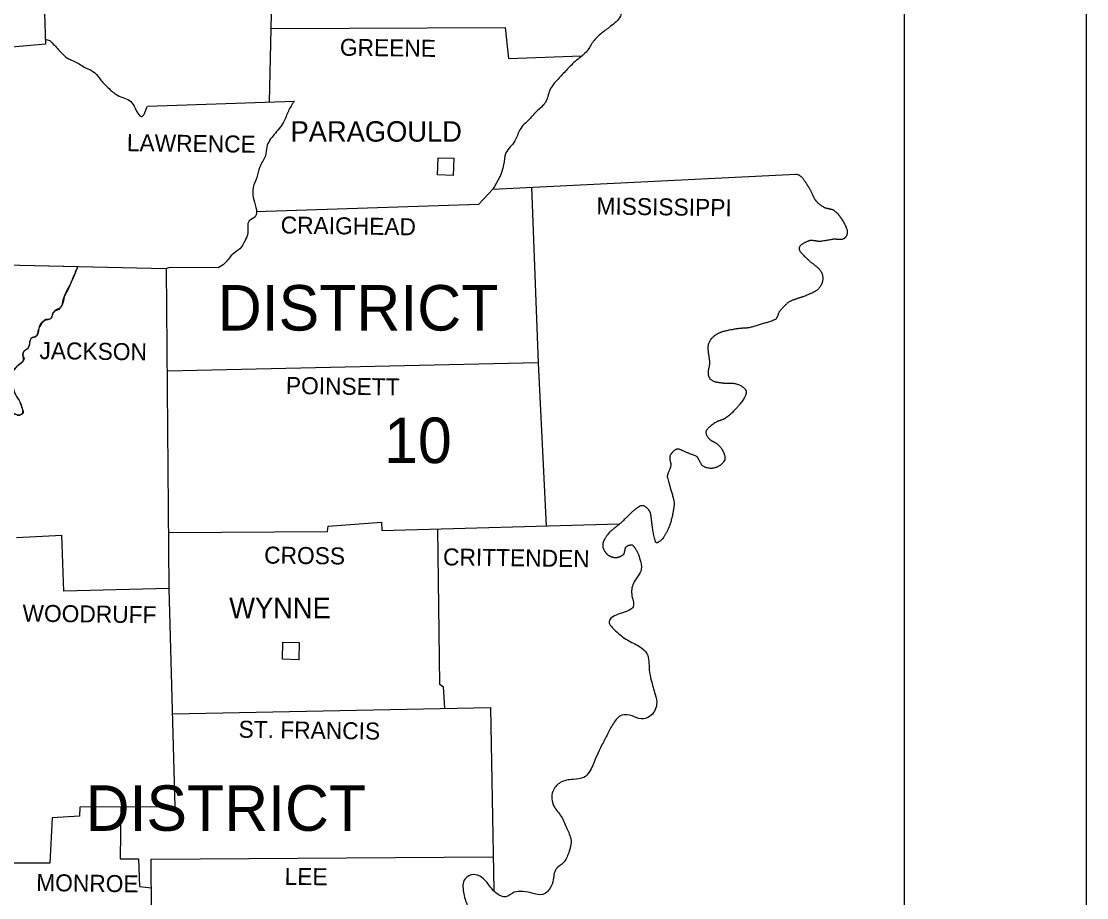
# Model space of a CAD drawing. Extents: x 840176 to 859715, y 1589036 to 1600368.
# Drawn here: x 855714 to 857176, y 1597585 to 1598788 of the extents above; entities that cross this region are included whole.
import ezdxf

# ---------------------------------------------------------------- set-up
doc = ezdxf.new("R2010")
doc.units = 0
for name, color, linetype in [('DSN_DRFT_Border', 7, 'Continuous'), ('SHET_Border-Text', 7, 'Continuous'), ('SHET_Stamp-Prelim', 7, 'Continuous')]:
    doc.layers.add(name, color=color, linetype=linetype)

msp = doc.modelspace()

# ---------------------------------------------------------------- linework, layer by layer
at = {"layer": 'DSN_DRFT_Border'}
for p, q in [((855753, 1598761.2), (855746.5, 1598763.1)), ((856088.1, 1598678.1), (856088.3, 1598678.4)), ((855706.8, 1598079.2), (855769.3, 1598082.6))]:
    msp.add_line(p, q, dxfattribs=at)
for points in [[(840175.5, 1600035.6), (840175.5, 1589035.6), (857175.5, 1589035.6), (857175.5, 1600035.6)], [(856284.8, 1598577), (856285.4, 1598600.6), (856306.9, 1598600), (856306.3, 1598576.4)], [(856071.9, 1597912.2), (856072.6, 1597935.9), (856095, 1597935.3), (856094.4, 1597911.6)]]:
    msp.add_lwpolyline(points, close=True, dxfattribs=at)
for points in [[(855654.4, 1598968.4), (855652.4, 1598951.7), (855663.3, 1598950.1), (855662.4, 1598943.9), (855675.1, 1598941.1), (855676.1, 1598932.1), (855682.3, 1598928.3), (855683.9, 1598902.2), (855715, 1598899.1), (855715.3, 1598875.1), (855726.8, 1598873.9), (855726.5, 1598864.5), (855736.5, 1598861.4), (855736.1, 1598829.7), (855744.5, 1598828.1), (855746.7, 1598756.6), (855700.4, 1598752.2), (855701, 1598737), (855687, 1598736), (855691.6, 1598453.7), (855912.3, 1598448.8), (855916, 1598009.3), (855771.9, 1598005.6), (855769.3, 1598082.6)], [(856054.1, 1598677.2), (856056.7, 1598797.9)], [(856056.3, 1598778), (856377.6, 1598779.6), (856381.9, 1598737), (856482.3, 1598740.4)], [(855886.5, 1598671.6), (856088.3, 1598678.4)], [(856360.7, 1598557.4), (856776.5, 1598578.2)], [(856035.9, 1598526.8), (856341.5, 1598536.8), (856360.7, 1598557.4)], [(856413.5, 1598560), (856422.7, 1598319.3), (856433.7, 1598095.2)], [(855983.9, 1598449.7), (855917.3, 1598450), (855912.3, 1598448.8)], [(856422.7, 1598319.3), (855913.5, 1598307.7)], [(855915.4, 1598086.2), (856133.9, 1598087.5), (856134.5, 1598094.9), (856207.9, 1598100.2), (856208.3, 1598089), (856534.6, 1598097.9)], [(856284.5, 1598091.1), (856287.6, 1597878), (856292.3, 1597874.6), (856294.3, 1597844.7)], [(855916, 1598009.3), (855924.4, 1597709.6), (855794, 1597709), (855793.4, 1597696.9), (855755.8, 1597694.4), (855752.6, 1597632.5), (855700.7, 1597632.1)], [(855920.9, 1597837.2), (856357.3, 1597846)], [(856357.3, 1597846), (856361.9, 1597595.2)], [(855850.1, 1597709.3), (855849.1, 1597638.1), (855874.3, 1597638.1), (855875.6, 1597600.4), (855892, 1597598.5)], [(855914.3, 1597152), (855965.5, 1597155.4), (855965.2, 1597266.2), (855924.7, 1597269.3), (855926.9, 1597486.5), (855892.7, 1597491.5), (855891.8, 1597637.8), (856361, 1597640.9)]]:
    msp.add_lwpolyline(points, dxfattribs=at)
for points in [[(856492.4, 1598984.7), (856495.2, 1598960.7), (856502.7, 1598948.3), (856503.9, 1598925.2), (856513.2, 1598915.3), (856529.1, 1598905.6), (856543.1, 1598889.4), (856546.2, 1598870.8), (856541.9, 1598851.8), (856540.9, 1598830.6), (856538.8, 1598812), (856535.6, 1598794.8), (856522.3, 1598781.1), (856509.8, 1598771.5), (856498.3, 1598760), (856490.2, 1598747.5), (856475.6, 1598734.5), (856461.6, 1598720.8), (856450.1, 1598708.6), (856438.9, 1598693.4), (856432.9, 1598676.6), (856420.8, 1598664.4), (856410.9, 1598653.5), (856397.5, 1598638.9), (856390.9, 1598623.7), (856378.5, 1598607.2), (856375.4, 1598590.7), (856360.7, 1598557.4)], [(855753, 1598761.2), (855764.8, 1598748.8), (855775.7, 1598738.2), (855787.5, 1598732.3), (855801.8, 1598724.2), (855814.3, 1598717.3), (855822.7, 1598707.1), (855833.9, 1598695.6), (855845.4, 1598686.5), (855863.7, 1598677.8), (855869.7, 1598668.5), (855878.1, 1598657), (855886.5, 1598671.6)], [(856088.1, 1598678.1), (856080, 1598664.7), (856073.5, 1598649.5), (856060.4, 1598632.4), (856050.5, 1598615.3), (856048.6, 1598603.4), (856040.8, 1598588.2), (856036.8, 1598573.3), (856031.8, 1598559.9), (856031.8, 1598546.2), (856035.5, 1598532.5), (856034.6, 1598519.7), (856026.2, 1598513.8), (856024.3, 1598497.9), (856020.6, 1598487), (856013.4, 1598475.8), (856003.2, 1598467.8), (855992.3, 1598455.3), (855983.9, 1598449.7)], [(855790.8, 1598451.5), (855780.6, 1598426.7), (855772.6, 1598410.2), (855767.9, 1598395.9), (855757.3, 1598387.8), (855753.9, 1598380), (855744.9, 1598376.9), (855737.7, 1598366), (855734.6, 1598356.3), (855726.8, 1598352), (855722.8, 1598339.5), (855715.9, 1598333), (855716.2, 1598322.1), (855708.1, 1598314.6), (855701.6, 1598305.9), (855701.3, 1598293.5), (855704.4, 1598277.9), (855710, 1598268.3), (855714.7, 1598256.4), (855714.4, 1598248.7), (855700.7, 1598248.7), (855688.8, 1598246.8)], [(856562.1, 1598051), (856564.3, 1598035.5), (856554.6, 1598018.4), (856551.2, 1598001.6), (856553.1, 1597984.4), (856535.6, 1597975.1), (856520.1, 1597963.9), (856529.1, 1597951.1), (856545.3, 1597938.7), (856561.8, 1597929.7), (856572.1, 1597920), (856575.2, 1597897.9), (856578, 1597883.3), (856583.3, 1597864), (856585.4, 1597850), (856575.8, 1597833.8), (856564.3, 1597830.4), (856551.8, 1597834.4), (856537.5, 1597835.4), (856526, 1597824.2), (856517.9, 1597809.2), (856509.8, 1597793.7), (856503.6, 1597780.6), (856497.7, 1597766.6), (856485.5, 1597750.1), (856470.9, 1597747.3), (856453.2, 1597742.9), (856442.9, 1597730.8), (856444.5, 1597710.6), (856454.4, 1597696.6), (856462.2, 1597679.8), (856467.8, 1597664.8), (856464.7, 1597646.5), (856457.2, 1597632.8), (856447.6, 1597624.4), (856442.9, 1597606.9), (856436.1, 1597593.9), (856429.2, 1597589.5), (856416.1, 1597590.8), (856402.1, 1597593.3), (856390, 1597592.3), (856378.2, 1597586.1), (856366.7, 1597590.1), (856354.8, 1597602.9), (856345.2, 1597612.9), (856334, 1597616.6), (856322.5, 1597610.7), (856320.3, 1597592.6), (856325.6, 1597574), (856330.9, 1597548.7), (856325.9, 1597533.8), (856324, 1597508.3)]]:
    msp.add_spline(points, degree=3, dxfattribs=at)
msp.add_open_spline([(856776.5, 1598578.2), (856778.6, 1598577.9), (856780.6, 1598577), (856782.4, 1598575.7), (856784.3, 1598574.3), (856785.9, 1598572.7), (856787.1, 1598570.8), (856788.5, 1598568.8), (856789.8, 1598566.8), (856791.1, 1598564.7), (856791.7, 1598563.7), (856792.3, 1598562.6), (856793, 1598561.6), (856793.6, 1598560.6), (856794.3, 1598559.6), (856794.9, 1598558.6), (856795.7, 1598557.3), (856796.5, 1598555.9), (856797.2, 1598554.5), (856797.9, 1598553.1), (856798.4, 1598551.7), (856799.1, 1598550.3), (856799.7, 1598548.9), (856800.4, 1598547.5), (856801.1, 1598546.1), (856801.7, 1598544.7), (856802.6, 1598543.4), (856803.6, 1598542.1), (856806.8, 1598538.2), (856810.7, 1598535.2), (856815.1, 1598532.8), (856816.2, 1598532.2), (856817.3, 1598531.7), (856818.5, 1598531.4), (856819.8, 1598531.2), (856821, 1598530.9), (856822.2, 1598530.7), (856823.4, 1598530.4), (856824.6, 1598530.1), (856825.8, 1598529.8), (856827, 1598529.5), (856828.1, 1598528.9), (856829.1, 1598528.1), (856833.6, 1598524.6), (856836.7, 1598520.4), (856839.7, 1598515.7), (856842.6, 1598511.2), (856844.9, 1598506.8), (856846.5, 1598501.7), (856846.9, 1598500.7), (856847, 1598499.6), (856847, 1598498.6), (856847, 1598497.5), (856846.9, 1598496.4), (856846.6, 1598495.3), (856846.3, 1598494.2), (856845.9, 1598493.2), (856845.3, 1598492.2), (856845, 1598491.7), (856844.6, 1598491.3), (856844.2, 1598490.9), (856844, 1598490.7), (856843.8, 1598490.5), (856843.5, 1598490.4), (856843.3, 1598490.2), (856843.1, 1598490), (856842.8, 1598489.8), (856841.6, 1598489.1), (856840.3, 1598488.6), (856838.9, 1598488.4), (856837.6, 1598488.3), (856836.3, 1598488.2), (856835, 1598488.3), (856833.7, 1598488.4), (856832.4, 1598488.6), (856831.1, 1598488.7), (856830.5, 1598488.7), (856829.8, 1598488.8), (856829.2, 1598488.7), (856828.5, 1598488.7), (856827.9, 1598488.7), (856827.3, 1598488.6), (856824.4, 1598488.1), (856821.7, 1598487.7), (856818.9, 1598487.2), (856816.1, 1598486.7), (856813.2, 1598486.3), (856810.4, 1598485.8), (856809.1, 1598485.6), (856807.8, 1598485.7), (856806.4, 1598485.9), (856805.1, 1598486), (856803.7, 1598486.4), (856802.4, 1598486.6), (856801, 1598486.8), (856799.7, 1598486.9), (856798.3, 1598487), (856797.6, 1598487.1), (856797, 1598487), (856796.3, 1598486.9), (856795.6, 1598486.8), (856794.9, 1598486.7), (856794.3, 1598486.4), (856792.7, 1598485.9), (856791.2, 1598485.2), (856789.6, 1598484.5), (856788.1, 1598483.7), (856786.6, 1598482.8), (856785.1, 1598481.8), (856783.8, 1598481), (856782.8, 1598480), (856781.8, 1598478.8), (856781.4, 1598478.3), (856781.2, 1598477.7), (856781, 1598477.2), (856780.9, 1598476.9), (856780.8, 1598476.6), (856780.8, 1598476.3), (856780.8, 1598476.1), (856780.8, 1598475.8), (856780.9, 1598475.5), (856781.2, 1598474.2), (856781.7, 1598473), (856782.5, 1598471.9), (856783.5, 1598470.6), (856784.4, 1598469.3), (856785.6, 1598468.2), (856788, 1598465.7), (856790.5, 1598463.3), (856793, 1598460.9), (856794.3, 1598459.7), (856795.6, 1598458.5), (856797, 1598457.4), (856798.3, 1598456.3), (856799.7, 1598455.3), (856801, 1598454.3), (856802.4, 1598453.2), (856803.7, 1598452.1), (856805.1, 1598451), (856806.5, 1598449.9), (856807.7, 1598448.6), (856808.9, 1598447.2), (856809.8, 1598446.2), (856810.6, 1598445), (856811.2, 1598443.8), (856811.9, 1598442.5), (856812.4, 1598441.3), (856812.8, 1598439.9), (856813.1, 1598438.6), (856813.3, 1598437.3), (856813.5, 1598436), (856813.6, 1598434.8), (856813.5, 1598433.5), (856813.2, 1598432.3), (856812.7, 1598429.5), (856811.7, 1598426.9), (856810.3, 1598424.4), (856809.5, 1598423.1), (856808.7, 1598422), (856807.6, 1598420.9), (856806.6, 1598419.8), (856805.5, 1598418.8), (856804.2, 1598418), (856801.5, 1598416.3), (856798.7, 1598414.8), (856795.7, 1598413.6), (856792.9, 1598412.4), (856790, 1598411.2), (856787.1, 1598410.2), (856785.7, 1598409.6), (856784.2, 1598409.1), (856782.8, 1598408.6), (856781.3, 1598408.1), (856779.8, 1598407.7), (856778.4, 1598407.2), (856776.9, 1598406.7), (856775.4, 1598406.2), (856774, 1598405.7), (856772.5, 1598405.2), (856771.1, 1598404.6), (856769.7, 1598404), (856768.2, 1598403.2), (856766.7, 1598402.4), (856765.4, 1598401.3), (856764, 1598400.3), (856762.8, 1598399.2), (856761.6, 1598398), (856760.4, 1598396.8), (856759.3, 1598395.6), (856758.1, 1598394.3), (856757, 1598393.1), (856755.8, 1598391.9), (856754.7, 1598390.6), (856753.9, 1598389.6), (856753.3, 1598388.5), (856752.8, 1598387.4), (856752.3, 1598386.2), (856752, 1598385), (856751.5, 1598383.8), (856751, 1598382.6), (856750.5, 1598381.5), (856749.9, 1598380.4), (856749.3, 1598379.4), (856748.3, 1598378.6), (856747.3, 1598378.1), (856744.5, 1598376.9), (856741.8, 1598375.9), (856738.9, 1598375), (856736.1, 1598374.2), (856733.3, 1598373.4), (856730.5, 1598372.5), (856727.6, 1598371.6), (856724.7, 1598370.7), (856721.8, 1598369.9), (856718.9, 1598369), (856716, 1598368.2), (856713, 1598367.5), (856711.8, 1598367.2), (856710.5, 1598367), (856709.2, 1598366.9), (856707.9, 1598366.8), (856706.6, 1598366.7), (856705.3, 1598366.6), (856704, 1598366.5), (856702.7, 1598366.5), (856701.4, 1598366.4), (856700.1, 1598366.3), (856698.8, 1598366.1), (856697.5, 1598366), (856694.6, 1598365.6), (856691.7, 1598365.1), (856688.9, 1598364.6), (856686, 1598364.1), (856683.2, 1598363.5), (856680.4, 1598362.9), (856678.8, 1598362.5), (856677.3, 1598362.1), (856675.7, 1598361.7), (856674.2, 1598361.2), (856672.8, 1598360.7), (856671.3, 1598360), (856669.8, 1598359.3), (856668.4, 1598358.6), (856667.1, 1598357.7), (856666.3, 1598357.2), (856665.7, 1598356.7), (856665, 1598356.2), (856664.3, 1598355.7), (856663.6, 1598355.1), (856662.9, 1598354.5), (856660.8, 1598352.5), (856659.1, 1598350.3), (856657.7, 1598347.8), (856657, 1598346.6), (856656.6, 1598345.4), (856656.3, 1598344.1), (856656, 1598342.8), (856655.8, 1598341.5), (856655.8, 1598340.2), (856655.8, 1598338.5), (856655.8, 1598336.8), (856656, 1598335.1), (856656.2, 1598333.4), (856656.4, 1598331.7), (856656.7, 1598330), (856656.9, 1598328.4), (856657.2, 1598326.7), (856657.4, 1598325), (856657.7, 1598323.3), (856657.9, 1598321.6), (856658, 1598319.9), (856658.1, 1598318.2), (856657.8, 1598316.4), (856657.5, 1598314.6), (856657.2, 1598312.8), (856656.7, 1598311.1), (856656.4, 1598309.3), (856656.1, 1598307.6), (856655.9, 1598305.8), (856656, 1598304), (856656, 1598303.1), (856656.2, 1598302.3), (856656.5, 1598301.4), (856656.6, 1598300.9), (856656.8, 1598300.5), (856657, 1598300.1), (856657.2, 1598299.6), (856657.4, 1598299.2), (856657.6, 1598298.8), (856658.5, 1598297.3), (856659.7, 1598296.1), (856661.2, 1598295.1), (856662.6, 1598294.2), (856664.1, 1598293.5), (856665.7, 1598293.2), (856667.4, 1598292.9), (856669, 1598292.5), (856670.7, 1598292.3), (856672.4, 1598292.1), (856674, 1598291.8), (856675.7, 1598291.6), (856677, 1598291.4), (856678.3, 1598291.3), (856679.6, 1598291.3), (856681, 1598291.3), (856682.3, 1598291.3), (856683.6, 1598291.4), (856685, 1598291.4), (856686.3, 1598291.4), (856687.6, 1598291.4), (856688.9, 1598291.4), (856690.2, 1598291.2), (856691.6, 1598291), (856694.5, 1598290.4), (856697.3, 1598289.5), (856700.1, 1598288.2), (856701.4, 1598287.5), (856702.7, 1598286.7), (856703.9, 1598285.8), (856704.5, 1598285.3), (856705, 1598284.8), (856705.6, 1598284.3), (856706.1, 1598283.8), (856706.6, 1598283.2), (856707.1, 1598282.6), (856707.8, 1598281.7), (856708.1, 1598280.7), (856708.3, 1598279.7), (856708.5, 1598278.7), (856708.4, 1598277.5), (856708.1, 1598276.5), (856707.3, 1598274.4), (856706.5, 1598272.3), (856705.3, 1598270.4), (856703.5, 1598267.8), (856701.8, 1598265.3), (856699.8, 1598262.8), (856698.9, 1598261.5), (856697.9, 1598260.3), (856696.9, 1598259.1), (856695.9, 1598257.8), (856694.8, 1598256.7), (856693.7, 1598255.5), (856689.6, 1598251.1), (856685.3, 1598247), (856680.4, 1598243.4), (856679.4, 1598242.6), (856678.3, 1598242), (856677.1, 1598241.6), (856676, 1598241.1), (856674.8, 1598240.7), (856673.7, 1598240.3), (856672.5, 1598239.9), (856671.3, 1598239.5), (856670.1, 1598239.1), (856668.9, 1598238.7), (856667.8, 1598238.1), (856666.7, 1598237.5), (856664, 1598236), (856661.6, 1598234.2), (856659.2, 1598232.2), (856658.1, 1598231.3), (856657.1, 1598230.3), (856656, 1598229.2), (856655.1, 1598228.2), (856654.2, 1598227.1), (856653.6, 1598225.9), (856652.7, 1598224.3), (856653.1, 1598221.9), (856653.9, 1598220.1), (856655, 1598218), (856656.2, 1598216.1), (856658, 1598214.4), (856658.9, 1598213.6), (856659.7, 1598212.8), (856660.8, 1598212.2), (856661.8, 1598211.7), (856662.9, 1598211.1), (856663.9, 1598210.5), (856664.9, 1598210), (856666, 1598209.4), (856667, 1598208.9), (856668, 1598208.3), (856668.9, 1598207.5), (856669.8, 1598206.6), (856673.5, 1598203), (856676.1, 1598198.7), (856677.9, 1598194.2), (856679.3, 1598190.7), (856679.2, 1598185.9), (856676.9, 1598182.7), (856676.5, 1598182.1), (856676, 1598181.6), (856675.5, 1598181), (856675, 1598180.5), (856674.5, 1598180.1), (856674, 1598179.6), (856673, 1598178.7), (856672, 1598178), (856670.8, 1598177.3), (856668.6, 1598176), (856666.3, 1598175.2), (856663.9, 1598174.6), (856661.5, 1598174), (856658.9, 1598174.1), (856656.4, 1598174.5), (856653.9, 1598175), (856651.5, 1598175.8), (856649.2, 1598177.4), (856648, 1598178.3), (856647, 1598179.3), (856646.3, 1598180.6), (856645.5, 1598181.9), (856644.9, 1598183.3), (856644.2, 1598184.6), (856643.5, 1598185.9), (856642.8, 1598187.2), (856642.1, 1598188.5), (856641.4, 1598189.6), (856640.2, 1598190.5), (856639, 1598191.1), (856635.1, 1598192.8), (856631, 1598194.1), (856627.1, 1598195.8), (856623.6, 1598197.2), (856620.1, 1598199), (856616.6, 1598200.4), (856615.6, 1598200.8), (856614.4, 1598200.8), (856613.4, 1598200.6), (856612.3, 1598200.3), (856611.2, 1598199.9), (856610.3, 1598199.1), (856609.2, 1598198.3), (856608.2, 1598197.5), (856607.3, 1598196.5), (856606.9, 1598196), (856606.4, 1598195.5), (856606, 1598194.9), (856605.5, 1598194.4), (856605.1, 1598193.9), (856604.7, 1598193.3), (856604, 1598192.1), (856603.4, 1598190.7), (856603.3, 1598189.4), (856603.3, 1598188.1), (856603.4, 1598186.7), (856603.7, 1598185.5), (856604, 1598184.1), (856604.3, 1598182.9), (856604.6, 1598181.5), (856604.7, 1598180.9), (856604.8, 1598180.3), (856604.8, 1598179.6), (856604.9, 1598179), (856604.9, 1598178.3), (856604.7, 1598177.7), (856604.5, 1598176.2), (856604, 1598174.8), (856603.5, 1598173.4), (856602.9, 1598172), (856602.2, 1598170.6), (856601.7, 1598169.1), (856601.1, 1598167.7), (856600.7, 1598166.3), (856600.3, 1598164.8), (856600, 1598163.5), (856600, 1598162), (856600.4, 1598160.6), (856601.6, 1598156.3), (856602.9, 1598152.1), (856604.1, 1598147.8), (856605.7, 1598142.1), (856607.4, 1598136.5), (856608.8, 1598130.7), (856609.8, 1598126.5), (856609.2, 1598121.9), (856608.5, 1598117.6), (856607.4, 1598111.2), (856606.1, 1598104.9), (856604.1, 1598098.7), (856603.6, 1598096.9), (856603, 1598095.3), (856602.3, 1598093.6), (856601.6, 1598092), (856600.9, 1598090.3), (856600.1, 1598088.8), (856599.3, 1598087.2), (856598.4, 1598085.6), (856597.6, 1598084.1), (856596.7, 1598082.5), (856595.8, 1598080.9), (856594.8, 1598079.4), (856593.3, 1598077), (856591.3, 1598075.3), (856589, 1598073.6), (856588, 1598072.9), (856586.9, 1598072.5), (856585.8, 1598072.2), (856585.4, 1598072.1), (856585, 1598072.2), (856584.6, 1598072.4), (856584.2, 1598072.7), (856584, 1598073), (856583.9, 1598073.4), (856582.8, 1598076.9), (856581.9, 1598080.2), (856581.3, 1598083.7), (856580.7, 1598087.3), (856580, 1598090.8), (856579.5, 1598094.3), (856579.2, 1598097.1), (856578.8, 1598099.9), (856578.5, 1598102.7), (856578.3, 1598104.1), (856578.2, 1598105.5), (856578, 1598106.9), (856577.9, 1598108.3), (856577.6, 1598109.7), (856577.4, 1598111.1), (856577.2, 1598112.1), (856576.9, 1598113), (856576.5, 1598113.9), (856576.1, 1598114.8), (856575.6, 1598115.7), (856575.1, 1598116.5), (856574.5, 1598117.4), (856573.8, 1598118.1), (856573.2, 1598118.9), (856572.4, 1598119.7), (856571.7, 1598120.4), (856570.8, 1598121.1), (856569.4, 1598122.1), (856567.8, 1598122.8), (856566.3, 1598122.9), (856564.8, 1598123.1), (856563.1, 1598122.8), (856561.8, 1598122), (856560.8, 1598121.4), (856559.8, 1598120.7), (856558.9, 1598120), (856557.9, 1598119.3), (856557, 1598118.6), (856556, 1598117.9), (856554.1, 1598116.5), (856552.3, 1598114.9), (856550.6, 1598113.3), (856548.5, 1598111.2), (856546.3, 1598109.1), (856544.2, 1598107), (856542.1, 1598105), (856540, 1598102.9), (856537.8, 1598100.8), (856536.6, 1598099.6), (856535.3, 1598098.5), (856534, 1598097.4), (856532.6, 1598096.3), (856531.3, 1598095.3), (856530, 1598094.2), (856528.6, 1598093.1), (856527.3, 1598092), (856525.9, 1598090.9), (856524.6, 1598089.8), (856523.3, 1598088.6), (856522, 1598087.5), (856519.8, 1598085.5), (856518, 1598083.2), (856516.3, 1598080.8), (856515.5, 1598079.6), (856514.8, 1598078.4), (856514.1, 1598077.1), (856513.4, 1598075.9), (856512.8, 1598074.8), (856512.3, 1598073.4), (856511.8, 1598072.1), (856511.5, 1598070.7), (856511.4, 1598069.3), (856511.3, 1598067.9), (856511.5, 1598066.4), (856512, 1598064.9), (856512.6, 1598063.3), (856513.2, 1598061.8), (856514.1, 1598060.4), (856514.6, 1598059.7), (856515.1, 1598059), (856515.7, 1598058.3), (856516, 1598058), (856516.3, 1598057.6), (856516.6, 1598057.3), (856516.9, 1598057), (856517.2, 1598056.6), (856517.6, 1598056.3), (856518.5, 1598055.5), (856519.5, 1598054.8), (856520.6, 1598054.1), (856521.6, 1598053.5), (856522.6, 1598053.1), (856523.7, 1598052.8), (856524.7, 1598052.4), (856525.7, 1598052.2), (856526.7, 1598052.1), (856527.7, 1598052), (856528.7, 1598051.9), (856529.7, 1598052), (856530.5, 1598052), (856531.3, 1598052.1), (856532.1, 1598052.2), (856532.9, 1598052.4), (856533.6, 1598052.6), (856534.4, 1598052.9), (856535.2, 1598053.3), (856536, 1598053.6), (856536.7, 1598054), (856537.6, 1598054.4), (856538.3, 1598054.9), (856539.1, 1598055.4), (856539.9, 1598056), (856540.7, 1598056.8), (856541, 1598057.8), (856541.3, 1598058.9), (856541.5, 1598059.9), (856541.8, 1598060.9), (856542, 1598062), (856542.1, 1598063), (856542.4, 1598064.1), (856542.6, 1598065), (856543, 1598065.9), (856543.7, 1598066.6), (856544.4, 1598067.3), (856545.1, 1598067.7), (856545.8, 1598068.1), (856546.7, 1598068.5), (856547.6, 1598068.8), (856548.5, 1598069), (856549.3, 1598069.3), (856550.2, 1598069.4), (856551.1, 1598069.2), (856551.8, 1598069.1), (856552.5, 1598068.7), (856553.1, 1598068.2), (856553.6, 1598067.5), (856554.1, 1598066.9), (856554.6, 1598066.3), (856555.1, 1598065.6), (856555.5, 1598065), (856556, 1598064.3), (856556.9, 1598063), (856557.6, 1598061.6), (856558.4, 1598060.1), (856559.9, 1598057.2), (856561, 1598054.1), (856562.1, 1598051)], degree=3, dxfattribs=at)
at = {"layer": 'SHET_Border-Text'}
for points in [[(840175.5, 1589035.6), (857175.5, 1589035.6), (857175.5, 1600035.6), (840175.5, 1600035.6)], [(840425.5, 1589285.6), (856925.5, 1589285.6), (856925.5, 1599785.6), (840425.5, 1599785.6)]]:
    msp.add_lwpolyline(points, close=True, dxfattribs=at)
at = {"layer": 'SHET_Stamp-Prelim'}
msp.add_lwpolyline([(855355, 1598432.8), (855418.4, 1598490.5), (855615.4, 1598487.4), (855619.1, 1598450.9), (855691.6, 1598453.7), (855790.8, 1598451.5)], dxfattribs=at)
msp.add_open_spline([(855790.8, 1598451.5), (855787.4, 1598443.2), (855784, 1598435), (855780.6, 1598426.7), (855778.3, 1598421), (855775.2, 1598415.7), (855772.6, 1598410.2), (855770.4, 1598405.7), (855770.1, 1598400.4), (855767.9, 1598395.9), (855766, 1598391.9), (855760, 1598391), (855757.3, 1598387.8), (855755.6, 1598385.7), (855755.8, 1598382), (855753.9, 1598380), (855751.7, 1598377.8), (855747, 1598379.3), (855744.9, 1598376.9), (855741.9, 1598373.6), (855739.7, 1598369.9), (855737.7, 1598366), (855736.2, 1598363), (855736.2, 1598359.2), (855734.6, 1598356.3), (855733.2, 1598353.8), (855728.4, 1598354.3), (855726.8, 1598352), (855724.4, 1598348.6), (855724.9, 1598343), (855722.8, 1598339.5), (855721.2, 1598337), (855717.4, 1598335.6), (855715.9, 1598333), (855714.3, 1598330), (855718.5, 1598324.9), (855716.2, 1598322.1), (855714, 1598319.3), (855710.6, 1598317.4), (855708.1, 1598314.6), (855705.7, 1598311.9), (855703, 1598309.5), (855701.6, 1598305.9), (855700, 1598301.9), (855700.8, 1598297.6), (855701.3, 1598293.5), (855701.9, 1598288.3), (855702.4, 1598283), (855704.4, 1598277.9), (855705.8, 1598274.4), (855708.4, 1598271.6), (855710, 1598268.3), (855711.9, 1598264.4), (855713.3, 1598260.4), (855714.7, 1598256.4), (855715.5, 1598254), (855716.9, 1598250.5), (855714.4, 1598248.7), (855709.9, 1598245.5), (855705.2, 1598249.4), (855700.7, 1598248.7), (855696.7, 1598248), (855692.8, 1598247.4), (855688.8, 1598246.8)], degree=3, dxfattribs=at)

# ---------------------------------------------------------------- texts
at = {"layer": 'DSN_DRFT_Border'}
for s, height, rotation, p in [('GREENE', 23.34, 359.2711, (856150.6, 1598740.7)), ('LAWRENCE', 23.34, 359.2655, (855858.3, 1598609.7)), ('MISSISSIPPI', 23.341, 359.2098, (856502.7, 1598522.8)), ('CRAIGHEAD', 23.34, 359.1888, (856069.4, 1598496.7)), ('JACKSON', 23.34, 359.2575, (855738.4, 1598324.3)), ('POINSETT', 23.34, 359.1979, (856076.5, 1598276.4)), ('CROSS', 23.34, 359.3097, (856046.7, 1598043.6)), ('CRITTENDEN', 23.34, 359.2782, (856292.2, 1598041.1)), ('WOODRUFF', 23.34, 359.2708, (855715.1, 1597963.9)), ('ST. FRANCIS', 23.341, 359.1956, (856011.6, 1597804.6)), ('LEE', 23.34, 359.3634, (856074.8, 1597602.6)), ('MONROE', 23.34, 359.1697, (855733.9, 1597594.2))]:
    msp.add_text(s, height=height, rotation=rotation, dxfattribs=at).set_placement(p)
for s, height, p in [('PARAGOULD', 28.01, (856083, 1598622.7)), ('DISTRICT', 62.43, (855983.2, 1598363.4)), ('10', 62.43, (856211.4, 1598181.5)), ('WYNNE', 28.01, (855998.9, 1597968.6)), ('DISTRICT', 62.43, (855801.8, 1597676.7))]:
    msp.add_text(s, height=height, dxfattribs=at).set_placement(p)

doc.saveas('drawing.dxf')
